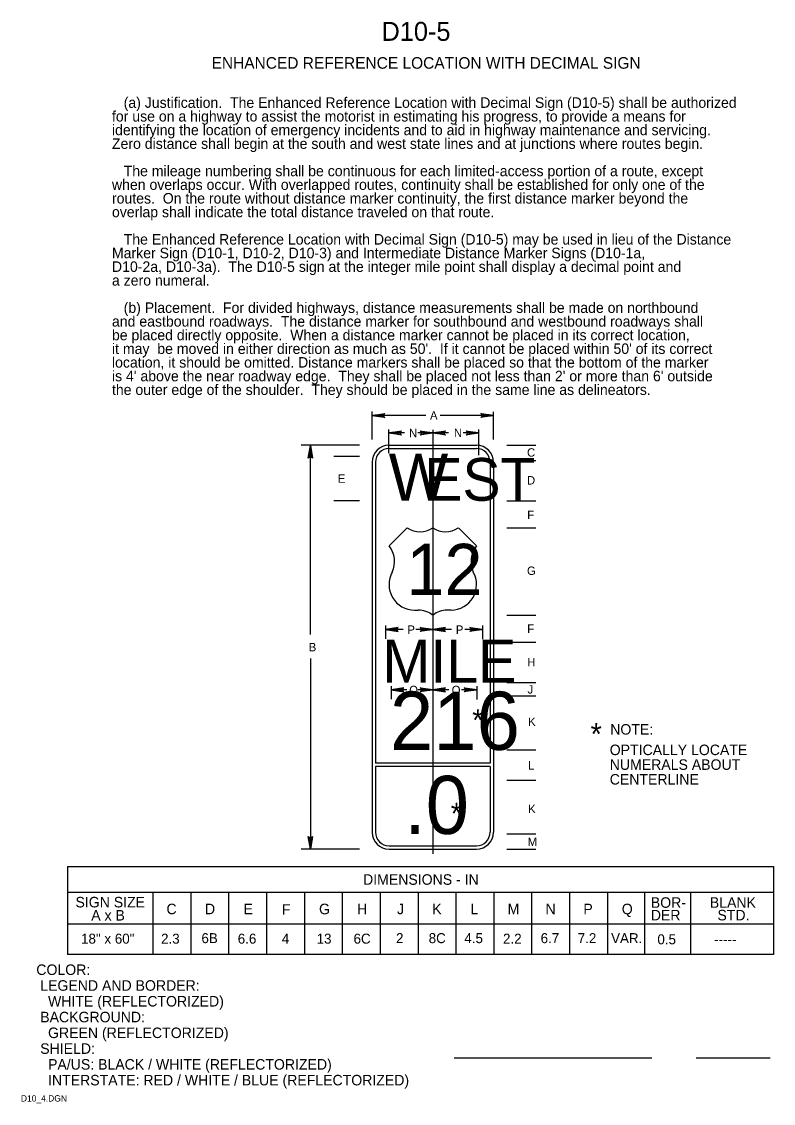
# Model space of a CAD drawing. Extents: x 0.013 to 0.191, y 0.006 to 0.263.
import ezdxf

# ---------------------------------------------------------------- set-up
doc = ezdxf.new("R2010")
doc.units = 0
for name, color, linetype in [('1', 7, 'Continuous'), ('2', 7, 'Continuous'), ('3', 7, 'Continuous')]:
    doc.layers.add(name, color=color, linetype=linetype)

# ---------------------------------------------------------------- blocks, each defined once
blk = doc.blocks.new('RARROW')
at = {"layer": '3'}
for p, q in [((-2.156, 0.28500000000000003), (-2.2665, 0.384625)), ((-2.2665, 0.384625), (0, 0)), ((0, 0), (-2.2665, -0.379125)), ((-2.156, 0.28500000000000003), (-2.075625, 0.12075)), ((0, 0), (-2.156, 0.28500000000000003)), ((-2.14975, -0.2705), (0, 0)), ((-2.075625, 0.12075), (0, 0)), ((0, 0), (-2.074, -0.108)), ((-2.2665, -0.379125), (-2.14975, -0.2705)), ((-2.074, -0.108), (-2.14975, -0.2705))]:
    blk.add_line(p, q, dxfattribs=at)

msp = doc.modelspace()

# ---------------------------------------------------------------- linework, layer by layer
at = {"layer": '1'}
for p, q in [((0.11543984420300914, 0.01694517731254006), (0.1624214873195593, 0.01694517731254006)), ((0.17295324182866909, 0.01694517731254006), (0.19056484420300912, 0.01694517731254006))]:
    msp.add_line(p, q, dxfattribs=at)
at = {"layer": '2'}
for p, q in [((0.1043118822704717, 0.14297684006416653), (0.10002524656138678, 0.13864776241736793)), ((0.11645027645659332, 0.14297684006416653), (0.12073691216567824, 0.13864776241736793)), ((0.12405270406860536, 0.12400691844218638), (0.12405270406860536, 0.12400691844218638)), ((0.10605200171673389, 0.12341110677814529), (0.10690084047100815, 0.12341110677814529)), ((0.11471015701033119, 0.12341110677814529), (0.11381887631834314, 0.12341110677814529))]:
    msp.add_line(p, q, dxfattribs=at)
for centre, radius, start, end in [((0.10733449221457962, 0.14731052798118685), 0.005289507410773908, 235.00798055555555, 304.9920222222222), ((0.11340115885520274, 0.14731052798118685), 0.005289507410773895, 235.0079777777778, 304.99201944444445), ((0.09521651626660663, 0.13492840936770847), 0.006066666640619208, 335.7034111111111, 38.02486944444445), ((0.12550284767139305, 0.1349222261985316), 0.006049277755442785, 141.9852277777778, 204.30668333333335), ((0.1060344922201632, 0.1294599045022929), 0.006066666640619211, 150.66324166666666, 270), ((0.11471088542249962, 0.1294662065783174), 0.006055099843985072, 269.99310833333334, 29.329866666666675), ((0.10686235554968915, 0.11781483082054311), 0.005596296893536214, 51.21564444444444, 89.87545277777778), ((0.11385215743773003, 0.11787505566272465), 0.005536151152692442, 90.34444166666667, 129.00425)]:
    msp.add_arc(centre, radius, start, end, dxfattribs=at)
at = {"layer": '3'}
for p, q in [((0.09596843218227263, 0.1639303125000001), (0.09596843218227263, 0.17060434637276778)), ((0.12476843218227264, 0.1639303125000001), (0.12476843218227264, 0.17055459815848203)), ((0.10874634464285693, 0.16964510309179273), (0.09596843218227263, 0.16964510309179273)), ((0.12476843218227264, 0.16964510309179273), (0.11210434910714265, 0.16964510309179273)), ((0.0999238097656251, 0.16069667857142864), (0.0999238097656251, 0.16632910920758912)), ((0.10367979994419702, 0.1654973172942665), (0.0999238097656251, 0.1654973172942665)), ((0.11036627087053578, 0.1654973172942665), (0.10682637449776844, 0.1654973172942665)), ((0.11412692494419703, 0.1654973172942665), (0.11036627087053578, 0.1654973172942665)), ((0.11036843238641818, 0.16624360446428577), (0.11036843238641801, 0.06547393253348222)), ((0.12128755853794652, 0.1654973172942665), (0.11757820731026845, 0.1654973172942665)), ((0.12128755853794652, 0.16019919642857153), (0.12128755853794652, 0.16632910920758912)), ((0.09294186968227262, 0.162577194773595), (0.0791107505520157, 0.162577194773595)), ((0.08127743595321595, 0.11760228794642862), (0.08127743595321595, 0.162577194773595)), ((0.09996843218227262, 0.162577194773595), (0.12076843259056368, 0.16257719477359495)), ((0.12795942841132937, 0.16257719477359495), (0.1348344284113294, 0.16257719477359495)), ((0.09294186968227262, 0.15993719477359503), (0.08683847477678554, 0.15993719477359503)), ((0.09996843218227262, 0.161777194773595), (0.12076843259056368, 0.16177719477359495)), ((0.09596843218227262, 0.15857719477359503), (0.09596843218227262, 0.07057719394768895)), ((0.09676843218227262, 0.15857719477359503), (0.09676843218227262, 0.08697719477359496)), ((0.12396843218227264, 0.15857719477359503), (0.12396843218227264, 0.08697719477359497)), ((0.12476843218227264, 0.15857719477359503), (0.12476843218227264, 0.07057719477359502)), ((0.12795942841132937, 0.15897719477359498), (0.1348344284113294, 0.15897719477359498)), ((0.09294186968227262, 0.149377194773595), (0.08683847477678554, 0.149377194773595)), ((0.12795942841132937, 0.14937719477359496), (0.1348344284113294, 0.14937719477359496)), ((0.12795942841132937, 0.142977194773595), (0.1348344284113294, 0.142977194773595)), ((0.12795942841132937, 0.12217719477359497), (0.1348344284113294, 0.12217719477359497)), ((0.09912472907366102, 0.11969637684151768), (0.09912472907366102, 0.11653736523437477)), ((0.10334399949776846, 0.11878802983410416), (0.09912472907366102, 0.11878802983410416)), ((0.11036379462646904, 0.11878802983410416), (0.10633511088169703, 0.11878802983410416)), ((0.11482339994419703, 0.11878802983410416), (0.11036379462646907, 0.11878802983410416)), ((0.12220790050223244, 0.11878802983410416), (0.11800728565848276, 0.11878802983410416)), ((0.12220790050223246, 0.11969637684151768), (0.12220790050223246, 0.11648761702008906)), ((0.12795942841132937, 0.11577719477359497), (0.1348344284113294, 0.11577719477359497)), ((0.08127743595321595, 0.11190611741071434), (0.08127743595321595, 0.06657719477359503)), ((0.12795942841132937, 0.10617719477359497), (0.1348344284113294, 0.10617719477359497)), ((0.10048036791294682, 0.10534417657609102), (0.10048036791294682, 0.10218516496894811)), ((0.10417106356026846, 0.1044358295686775), (0.10048036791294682, 0.1044358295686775)), ((0.11036379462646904, 0.1044358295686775), (0.10684503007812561, 0.1044358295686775)), ((0.11415179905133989, 0.1044358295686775), (0.11036379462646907, 0.1044358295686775)), ((0.12083982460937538, 0.1044358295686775), (0.11718644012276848, 0.1044358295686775)), ((0.1208398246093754, 0.10534417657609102), (0.1208398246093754, 0.10213541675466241)), ((0.12795942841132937, 0.10297719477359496), (0.1348344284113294, 0.10297719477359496)), ((0.12795942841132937, 0.09017719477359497), (0.1348344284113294, 0.09017719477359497)), ((0.12396843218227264, 0.08697719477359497), (0.09676843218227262, 0.08697719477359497)), ((0.09676843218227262, 0.08617719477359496), (0.09676843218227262, 0.07057719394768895)), ((0.12396843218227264, 0.08617719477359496), (0.09676843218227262, 0.08617719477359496)), ((0.12396843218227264, 0.08617719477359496), (0.12396843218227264, 0.07057719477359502)), ((0.12795942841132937, 0.08297719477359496), (0.1348344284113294, 0.08297719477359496)), ((0.12795942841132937, 0.07017719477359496), (0.1348344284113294, 0.07017719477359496)), ((0.09996843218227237, 0.06737719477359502), (0.12076847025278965, 0.06737719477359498)), ((0.09294186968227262, 0.06657719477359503), (0.0791107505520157, 0.06657719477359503)), ((0.09996843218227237, 0.06657719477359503), (0.12076847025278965, 0.06657719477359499)), ((0.12795942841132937, 0.06657719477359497), (0.1348344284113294, 0.06657719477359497)), ((0.023562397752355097, 0.062464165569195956), (0.19130417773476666, 0.062464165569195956)), ((0.023562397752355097, 0.062464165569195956), (0.023562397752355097, 0.04155334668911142)), ((0.1913041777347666, 0.062464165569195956), (0.1913041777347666, 0.04155334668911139)), ((0.1913041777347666, 0.05625334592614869), (0.023562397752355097, 0.05625334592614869)), ((0.043856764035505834, 0.05610237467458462), (0.043856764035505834, 0.04155334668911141)), ((0.052856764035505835, 0.05610237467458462), (0.052856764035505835, 0.04155334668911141)), ((0.061856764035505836, 0.05610237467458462), (0.061856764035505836, 0.04155334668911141)), ((0.07085676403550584, 0.05610237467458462), (0.07085676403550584, 0.04155334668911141)), ((0.07985676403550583, 0.05610237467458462), (0.07985676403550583, 0.04155334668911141)), ((0.08885676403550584, 0.05610237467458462), (0.08885676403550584, 0.04155334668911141)), ((0.09785676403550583, 0.05610237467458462), (0.09785676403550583, 0.04155334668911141)), ((0.10685676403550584, 0.05610237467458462), (0.10685676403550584, 0.04155334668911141)), ((0.11585676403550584, 0.05610237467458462), (0.11585676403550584, 0.04155334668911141)), ((0.1248567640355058, 0.05610237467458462), (0.1248567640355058, 0.04155334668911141)), ((0.1338567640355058, 0.05610237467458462), (0.1338567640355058, 0.04155334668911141)), ((0.14285676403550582, 0.05610237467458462), (0.14285676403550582, 0.04155334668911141)), ((0.15185676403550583, 0.05610237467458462), (0.15185676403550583, 0.04155334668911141)), ((0.1606834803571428, 0.05610237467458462), (0.1606834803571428, 0.04155334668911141)), ((0.1716115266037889, 0.05625334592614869), (0.1716115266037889, 0.04155334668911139)), ((0.023562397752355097, 0.04884484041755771), (0.19130417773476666, 0.04884484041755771)), ((0.1913041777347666, 0.04155334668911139), (0.023562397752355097, 0.04155334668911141))]:
    msp.add_line(p, q, dxfattribs=at)
for centre, radius, start, end in [((0.09996843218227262, 0.15857719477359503), 0.004, 90, 180), ((0.12076843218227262, 0.15857719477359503), 0.004, 0, 90), ((0.09996843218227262, 0.15857719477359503), 0.0032, 90, 180), ((0.12076843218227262, 0.15857719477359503), 0.0032, 0, 90), ((0.09996843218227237, 0.07057719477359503), 0.004, 180, 270), ((0.09996843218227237, 0.07057719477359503), 0.0032, 180, 270), ((0.12076843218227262, 0.07057719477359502), 0.004, 270, 0), ((0.12076843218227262, 0.07057719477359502), 0.0032, 270, 0)]:
    msp.add_arc(centre, radius, start, end, dxfattribs=at)

# ---------------------------------------------------------------- block references
at = {"layer": '3', "xscale": 0.0013236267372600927}
for p, yscale, rotation in [((0.09596843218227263, 0.16964510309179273), 0.001309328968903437, 180), ((0.0999238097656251, 0.1654973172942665), 0.001309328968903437, 180), ((0.11036627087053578, 0.1654973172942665), 0.001309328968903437, 180), ((0.08127743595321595, 0.1624958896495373), 0.001309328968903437, 90), ((0.09912472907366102, 0.11878802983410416), -0.001309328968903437, 180), ((0.11036379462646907, 0.11878802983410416), -0.001309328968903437, 180), ((0.10048036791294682, 0.1044358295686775), -0.001309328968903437, 180), ((0.11036379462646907, 0.1044358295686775), -0.001309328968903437, 180), ((0.08127743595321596, 0.06657719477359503), 0.001309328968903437, -90)]:
    msp.add_blockref('RARROW', p, dxfattribs=dict(at, yscale=yscale, rotation=rotation))
at = {"layer": '3', "xscale": 0.0013236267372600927, "yscale": 0.001309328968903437}
for p in [(0.12476843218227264, 0.1696451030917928), (0.11036627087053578, 0.1654973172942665), (0.12128755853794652, 0.1654973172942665), (0.11036379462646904, 0.11878802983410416), (0.12220790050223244, 0.11878802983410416), (0.11036379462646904, 0.1044358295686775), (0.12083982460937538, 0.1044358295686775)]:
    msp.add_blockref('RARROW', p, dxfattribs=at)

# ---------------------------------------------------------------- texts
at = {"layer": '1'}
for s, height, p in [('D10-5', 0.0045000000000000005, (0.09818501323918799, 0.2587015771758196)), ('ENHANCED REFERENCE LOCATION WITH DECIMAL SIGN', 0.00275025, (0.05780386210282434, 0.25207657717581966)), ('COLOR: ', 0.0024997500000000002, (0.01615434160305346, 0.03666212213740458)), (' LEGEND AND BORDER:', 0.0024997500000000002, (0.01615434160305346, 0.03291237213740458)), ('   WHITE (REFLECTORIZED)', 0.0024997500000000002, (0.01615434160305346, 0.02916262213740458)), (' BACKGROUND:', 0.0024997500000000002, (0.01615434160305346, 0.025412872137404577)), ('   GREEN (REFLECTORIZED)', 0.0024997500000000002, (0.01615434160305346, 0.021663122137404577)), (' SHIELD: ', 0.0024997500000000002, (0.01615434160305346, 0.01791337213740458)), ('   PA/US: BLACK / WHITE (REFLECTORIZED)', 0.0024997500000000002, (0.01615434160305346, 0.01416362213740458)), ('   INTERSTATE: RED / WHITE / BLUE (REFLECTORIZED)', 0.0024997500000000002, (0.01615434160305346, 0.010413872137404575)), ('D10_4.DGN', 0.0015, (0.0125, 0.006574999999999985))]:
    msp.add_text(s, height=height, dxfattribs=at).set_placement(p)
at = {"layer": '2'}
for s, p in [('   (a) Justification.  The Enhanced Reference Location with Decimal Sign (D10-5) shall be authorized ', (0.034127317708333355, 0.24277552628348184)), ('for use on a highway to assist the motorist in estimating his progress, to provide a means for ', (0.034127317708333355, 0.23952577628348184)), ('identifying the location of emergency incidents and to aid in highway maintenance and servicing.  ', (0.034127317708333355, 0.23627602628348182)), ('Zero distance shall begin at the south and west state lines and at junctions where routes begin.', (0.034127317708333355, 0.23302627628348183)), ('   The mileage numbering shall be continuous for each limited-access portion of a route, except', (0.034127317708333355, 0.22652677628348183)), ('when overlaps occur. With overlapped routes, continuity shall be established for only one of the', (0.034127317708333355, 0.22327702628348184)), ('routes.  On the route without distance marker continuity, the first distance marker beyond the', (0.034127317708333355, 0.22002727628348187)), ('overlap shall indicate the total distance traveled on that route.', (0.034127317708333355, 0.21677752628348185)), ('   The Enhanced Reference Location with Decimal Sign (D10-5) may be used in lieu of the Distance ', (0.034127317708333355, 0.21027802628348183)), ('Marker Sign (D10-1, D10-2, D10-3) and Intermediate Distance Marker Signs (D10-1a, ', (0.034127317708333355, 0.20702827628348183)), ('D10-2a, D10-3a).  The D10-5 sign at the integer mile point shall display a decimal point and ', (0.034127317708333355, 0.20377852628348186)), ('a zero numeral.', (0.034127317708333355, 0.20052877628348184)), ('   (b) Placement.  For divided highways, distance measurements shall be made on northbound', (0.034127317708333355, 0.19402927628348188)), ('and eastbound roadways.  The distance marker for southbound and westbound roadways shall', (0.034127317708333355, 0.19077952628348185)), ('be placed directly opposite.  When a distance marker cannot be placed in its correct location,', (0.034127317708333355, 0.18752977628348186)), ("it may  be moved in either direction as much as 50'.  If it cannot be placed within 50' of its correct ", (0.034127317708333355, 0.18428002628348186)), ('location, it should be omitted. Distance markers shall be placed so that the bottom of the marker', (0.034127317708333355, 0.18103027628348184)), ("is 4' above the near roadway edge.  They shall be placed not less than 2' or more than 6' outside ", (0.034127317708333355, 0.17778052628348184)), ('the outer edge of the shoulder.  They should be placed in the same line as delineators. ', (0.034127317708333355, 0.17453077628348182))]:
    msp.add_text(s, height=0.0024997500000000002, dxfattribs=at).set_placement(p)
at = {"layer": '3'}
for s, height, p in [('A', 0.00200025, (0.109714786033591, 0.16867559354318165)), ('N', 0.00200025, (0.11539317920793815, 0.1645410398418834)), ('C', 0.00200025, (0.13276666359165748, 0.15985668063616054)), ('D', 0.00200025, (0.13276666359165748, 0.15324016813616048)), ('F', 0.00200025, (0.13281391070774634, 0.14503171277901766)), ('G', 0.00200025, (0.13276666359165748, 0.131748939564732)), ('P', 0.00200025, (0.1043439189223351, 0.11774758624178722)), ('F', 0.00200025, (0.13281391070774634, 0.1179686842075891)), ('MILE', 0.010194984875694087, (0.09840858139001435, 0.10615208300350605)), ('H', 0.00200025, (0.13282184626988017, 0.11000896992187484)), ('Q', 0.00200025, (0.10476646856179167, 0.10339538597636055)), ('J', 0.00200025, (0.1328926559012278, 0.10354170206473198)), ('*', 0.005152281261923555, (0.11974592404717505, 0.09468690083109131)), ('*', 0.005152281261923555, (0.1478661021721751, 0.09137864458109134)), ('NOTE:', 0.0024997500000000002, (0.15253974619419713, 0.09379310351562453)), ('OPTICALLY LOCATE ', 0.0024997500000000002, (0.15242061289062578, 0.08891787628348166)), ('NUMERALS ABOUT ', 0.0024997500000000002, (0.15242061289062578, 0.08541812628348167)), ('CENTERLINE', 0.0024997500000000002, (0.15242061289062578, 0.08191837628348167)), ('*', 0.005152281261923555, (0.1146467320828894, 0.07247432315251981)), ('DIMENSIONS - IN', 0.0024997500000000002, (0.09379639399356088, 0.058102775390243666)), ('SIGN SIZE', 0.0024997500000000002, (0.025456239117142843, 0.05272273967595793)), ('BOR-', 0.0024997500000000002, (0.1621830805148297, 0.05262690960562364)), ('BLANK', 0.0024997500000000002, (0.1762106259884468, 0.052637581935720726)), ('A x B', 0.0024997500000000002, (0.029206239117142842, 0.04959773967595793)), ('C', 0.0024997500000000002, (0.04708123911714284, 0.05109773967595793)), ('D', 0.0024997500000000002, (0.05623677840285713, 0.05109773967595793)), ('E', 0.0024997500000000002, (0.06539720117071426, 0.05109773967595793)), ('F', 0.0024997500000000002, (0.0745023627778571, 0.05097273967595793)), ('G', 0.0024997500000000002, (0.08333942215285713, 0.05109773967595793)), ('H', 0.0024997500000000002, (0.0923682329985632, 0.05109773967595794)), ('J', 0.0024997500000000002, (0.10187912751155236, 0.05109773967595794)), ('K', 0.0024997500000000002, (0.11023946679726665, 0.05109773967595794)), ('M', 0.0024997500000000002, (0.1281557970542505, 0.05109773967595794)), ('N', 0.0024997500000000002, (0.1371535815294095, 0.05109773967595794)), ('P', 0.0024997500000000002, (0.14615319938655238, 0.05109773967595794)), ('Q', 0.0024997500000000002, (0.15528062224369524, 0.05109773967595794)), ('DER', 0.0024997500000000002, (0.1621830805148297, 0.04962715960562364)), ('STD.', 0.0024997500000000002, (0.17801044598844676, 0.04963783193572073)), ('18" x 60"', 0.0023752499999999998, (0.02679258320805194, 0.04410105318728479)), ('2.3', 0.0023752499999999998, (0.04580617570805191, 0.04410105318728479)), ('6B', 0.0023752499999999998, (0.05539678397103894, 0.04422605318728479)), ('6.6', 0.0023752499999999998, (0.06402547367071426, 0.04410105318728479)), ('4', 0.0023752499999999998, (0.07449048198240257, 0.04410105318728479)), ('13', 0.0023752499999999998, (0.0827689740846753, 0.04410105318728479)), ('6C', 0.0023752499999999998, (0.09154407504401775, 0.0441010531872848)), ('2', 0.0023752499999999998, (0.10164124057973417, 0.0442260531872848)), ('4.5', 0.0023752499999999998, (0.11788114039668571, 0.0442260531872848)), ('2.2', 0.0023752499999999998, (0.12706245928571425, 0.04410105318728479)), ('7.2', 0.0023752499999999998, (0.1448150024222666, 0.0442260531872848)), ('VAR.', 0.0023752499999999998, (0.1527460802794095, 0.0442260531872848)), ('0.5', 0.0023752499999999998, (0.16374802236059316, 0.043950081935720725)), ('-----', 0.0023752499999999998, (0.17724322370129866, 0.043950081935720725))]:
    msp.add_text(s, height=height, dxfattribs=at).set_placement(p)
for s, height, p in [('N', 0.00200025, (0.10472008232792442, 0.16448114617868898)), ('W', 0.011217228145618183, (0.09988386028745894, 0.1493642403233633)), ('EST', 0.010153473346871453, (0.10835943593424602, 0.14939011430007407)), ('E', 0.00200025, (0.08780600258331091, 0.15365706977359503)), ('12', 0.01215924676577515, (0.10410617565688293, 0.12698474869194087)), ('P', 0.00200025, (0.11586358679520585, 0.11774758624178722)), ('B', 0.00200025, (0.0809046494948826, 0.11357706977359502)), ('Q', 0.00200025, (0.11487453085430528, 0.10339538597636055)), ('216', 0.013837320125, (0.10019620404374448, 0.09016672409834)), ('K', 0.00200025, (0.13303167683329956, 0.09585443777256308)), ('L', 0.00200025, (0.13303167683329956, 0.0854862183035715)), ('.0', 0.013810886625, (0.10356438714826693, 0.07017263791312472)), ('K', 0.00200025, (0.13303167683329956, 0.07513342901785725)), ('M', 0.00200025, (0.13292924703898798, 0.06730307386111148)), ('L', 0.0024997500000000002, (0.11930528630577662, 0.05109773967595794)), ('8C', 0.0023752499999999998, (0.10939637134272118, 0.0442260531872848)), ('6.7', 0.0023752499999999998, (0.13600212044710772, 0.0442260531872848))]:
    msp.add_text(s, height=height, rotation=360, dxfattribs=at).set_placement(p)

doc.saveas('drawing.dxf')
